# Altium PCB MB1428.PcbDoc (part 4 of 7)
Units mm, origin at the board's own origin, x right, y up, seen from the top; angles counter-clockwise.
Board outline 55.88 x 152.4 mm, 4 copper layers (Top Layer, Signal Layer 1, Signal Layer 2, Bottom Layer), stack 1.614 mm thick; 396 components, 227 nets, 1346 pads, 1469 vias.
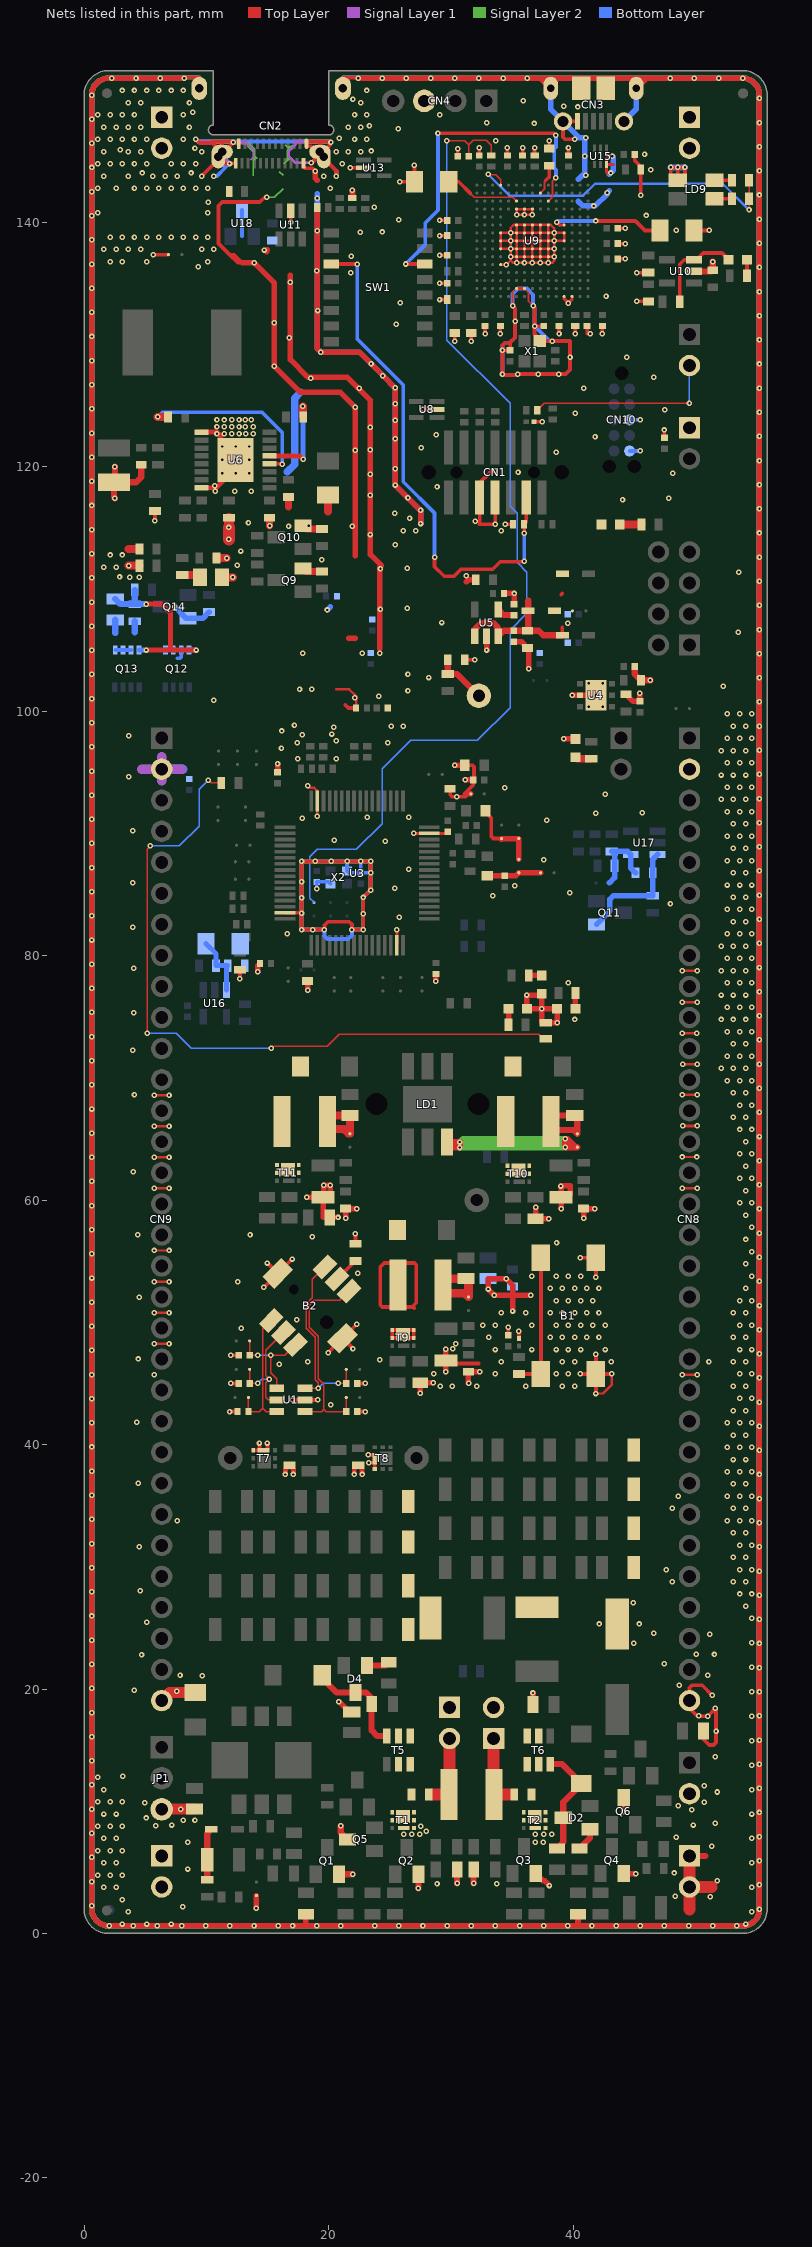
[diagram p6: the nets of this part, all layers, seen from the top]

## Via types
v1: diameter 0.45, hole 0.2, Top Layer to Bottom Layer, tented both sides, 1460 vias
v2: diameter 0.6, hole 0.2, Top Layer to Bottom Layer, tented both sides, 9 vias

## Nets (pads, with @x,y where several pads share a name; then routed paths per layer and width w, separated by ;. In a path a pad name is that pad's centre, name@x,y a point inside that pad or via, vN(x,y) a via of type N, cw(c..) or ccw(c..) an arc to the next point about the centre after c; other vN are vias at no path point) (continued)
GND: B1.3 B1.4 B2.7 B2.8 C4.1 C5.1 C6.1 C7.2 C8.1 C9.1 C10.1 C11.1 C12.1 C13.1 C14.1 C15.1 C16.1 C18.1 C19.1 C23.1 C24.1 C25.1 C30.1 C32.1 C33.1 C34.1 C35.1 C36.1 C37.1 C38.1 C39.1 C40.1 C41.1 C42.1 C43.1 C44.1 C45.1 C46.1 C47.1 C48.1 C49.1 C51.2 C52.1 C53.1 C54.1 C55.1 C56.1 C59.1 C60.1 C61.1 C62.1 C63.1 C64.1 C65.1 C66.1 C67.1 C68.1 C69.1 C70.1 C71.1 C72.1 C73.1 C74.1 C75.1 C76.1 C77.1 C78.1 C79.1 C80.1 C81.1 C82.1 C83.1 C84.1 C85.1 C86.1 C87.1 C89.1 C92.1 C93.1 C97.1 C98.1 C99.1 C100.1 C101.1 C103.1 C104.1 C105.1 CN1.5 CN1.7 CN2.1 CN2.2 CN2.3 CN2.4 CN2.5 CN2.6 CN2.A1 CN2.A12 CN2.B1 CN2.B12 CN3.5 CN3.6 CN3.7 CN3.8 CN3.9 CN3.10 CN3.11 CN4.3 CN5.1 CN5.2 CN6.1 CN6.2 CN7.2 CN8.2 CN8.32 CN9.2 CN9.32 CN10.3 CN10.5 CN11.1 CN11.2 CN12.1 CN12.2 JP1.3 JP6.1 L7.1 LD2.2 LD3.2 LD4.2 LD5.2 LD6.2 LD7.2 LD9.1 Q1.2 Q2.2 Q3.2 Q4.2 Q5.3 Q6.3 Q9.2 Q10.2 Q14.2 R1.1 R7.1 R12.1 R13.1 R59.1 R60.1 R66.1 R68.1 R70.1 R71.1 R73.1 R76.1 R77.1 R83.1 R98.1 R101.1 R103.1 R106.1 R108.1 R109.1 R118.1 R120.1 R122.2 R124.1 R126.2 R131.1 R135.1 R141.1 SB1.2 SB25.1 SB32.1 T1.4 T1.7 T2.4 T2.7 T7.4 T7.7 T8.4 T8.7 U1.2 U2.2 U3.15 U3.31 U3.47 U3.63 U4.2 U4.EP U5.2 U6.1 U6.8 U6.17 U7.2 U8.2 U9.D5 U9.D7 U9.D8 U9.D9 U9.F2 U9.F6 U9.F7 U9.F8 U9.F9 U9.F10 U9.F12 U9.G2 U9.G6 U9.G7 U9.G8 U9.G9 U9.G10 U9.G12 U9.H6 U9.H7 U9.H8 U9.H9 U9.H10 U9.H12 U9.J6 U9.J7 U9.J8 U9.J9 U9.J10 U9.K6 U9.K7 U9.K8 U9.K9 U9.K10 U9.M1 U9.M8 U9.M9 U9.N1 U10.2 U11.2 U12.2 U13.2 U14.2 U15.3 U18.3 X1.2 X2.2 X2.4 | length 1905
  Top Layer w0.15: v1(35.055,133.15) 35.055,134.25 U9.F2@35.38,134.575 ; U9.G2@36.03,134.575 36.36,134.245 36.36,133.52 v1(36.73,133.15)
  Top Layer w0.2: v1(5.75,48.25) v1(6.95,48.25) ; v1(5.75,50.8) v1(6.95,50.8) ; v1(5.75,53.325) v1(6.95,53.325) ; v1(5.75,55.875) v1(6.95,55.875) ; v1(5.75,60.95) v1(6.95,60.95) ; v1(5.75,63.5) v1(6.95,63.5) ; v1(5.75,66.025) v1(6.95,66.025) ; v1(5.75,68.575) v1(6.95,68.575) ; CN2.A1@17.945,144.53 17.945,144.555 CN2.A1@17.945,144.82 ; v1(18.289,93.879) 18.444,93.724 18.83,93.724 19.089,93.465 U3.47@19.089,92.654 v1(19.089,91.404) ; 20.645,101.78 21.695,101.78 22.25,101.225 C37.1@22.25,100.25 ; v1(29.595,47.8) v1@29.689,47.8 ; U9.D5@34.08,136.525 v1(34.555,136.525) 34.905,136.875 ; v1(41.875,44.175) 42.449,44.175 43.175,44.901 v1(43.175,45.775) ; v1(48.925,63.525) v1(50.125,63.525) ; v1(48.925,73.65) v1(50.125,73.65) ; v1(48.95,45.7) v1(50.15,45.7) ; v1(48.95,60.95) v1(50.15,60.95) ; v1(48.95,68.6) v1(50.15,68.6) ; v1(48.95,76.2) v1(50.15,76.2) ; v1(48.95,78.75) v1(50.15,78.75) ; v1(48.975,71.125) v1(50.175,71.125) ; U9.D8@34.08,138.475 v1(34.905,138.475) ; U9.D8@34.08,138.475 U9.D7@34.08,137.825 v1(34.905,137.825) ; U9.D8@34.08,138.475 U9.D9@34.08,139.125 v1(34.905,139.125) ; 34.905,136.875 v1(34.905,137.175) ; 34.905,136.875 35.08,136.7 v1(35.38,136.7) ; v1(34.905,137.175) U9.F6@35.38,137.175 ; v1(34.905,137.175) v1(34.905,137.825) ; v1(34.905,137.825) U9.F7@35.38,137.825 ; v1(34.905,137.825) v1(34.905,138.475) ; v1(34.905,138.475) U9.F8@35.38,138.475 ; v1(34.905,138.475) v1(34.905,139.125) ; v1(34.905,139.125) U9.F9@35.38,139.125 ; v1(34.905,139.125) 34.905,139.55 35.13,139.775 U9.F10@35.38,139.775 ; v1(35.38,136.7) U9.F6@35.38,137.175 ; v1(35.38,136.7) v1(36.03,136.7) ; U9.F6@35.38,137.175 U9.G6@36.03,137.175 ; U9.F6@35.38,137.175 U9.F7@35.38,137.825 ; U9.F7@35.38,137.825 U9.F8@35.38,138.475 ; U9.F7@35.38,137.825 U9.G7@36.03,137.825 ; U9.F8@35.38,138.475 U9.F9@35.38,139.125 ; U9.F8@35.38,138.475 U9.G8@36.03,138.475 ; U9.F9@35.38,139.125 U9.F10@35.38,139.775 ; U9.F9@35.38,139.125 U9.G9@36.03,139.125 ; U9.F10@35.38,139.775 U9.G10@36.03,139.775 ; v1(36.03,136.7) U9.G6@36.03,137.175 ; v1(36.03,136.7) v1(36.68,136.7) ; U9.G6@36.03,137.175 U9.H6@36.68,137.175 ; U9.G6@36.03,137.175 U9.G7@36.03,137.825 ; U9.G7@36.03,137.825 U9.G8@36.03,138.475 ; U9.G7@36.03,137.825 U9.H7@36.68,137.825 ; U9.G8@36.03,138.475 U9.G9@36.03,139.125 ; U9.G8@36.03,138.475 U9.H8@36.68,138.475 ; U9.G9@36.03,139.125 U9.G10@36.03,139.775 ; U9.G9@36.03,139.125 U9.H9@36.68,139.125 ; U9.G10@36.03,139.775 U9.H10@36.68,139.775 ; v1(36.03,140.6) U9.G12@36.03,141.075 ; v1(36.03,140.6) v1(36.68,140.6) U9.H12@36.68,141.075 U9.G12@36.03,141.075 ; v1(36.03,140.6) v1(35.38,140.6) U9.F12@35.38,141.075 U9.G12@36.03,141.075 ; v1(36.68,136.7) U9.H6@36.68,137.175 ; v1(36.68,136.7) v1(37.33,136.7) ; U9.H6@36.68,137.175 U9.J6@37.33,137.175 ; U9.H6@36.68,137.175 U9.H7@36.68,137.825 ; U9.H7@36.68,137.825 U9.H8@36.68,138.475 ; U9.H7@36.68,137.825 U9.J7@37.33,137.825 ; U9.H8@36.68,138.475 U9.H9@36.68,139.125 ; U9.H8@36.68,138.475 U9.J8@37.33,138.475 ; U9.H9@36.68,139.125 U9.H10@36.68,139.775 ; U9.H9@36.68,139.125 U9.J9@37.33,139.125 ; U9.H10@36.68,139.775 U9.J10@37.33,139.775 ; v1(37.33,136.7) U9.J6@37.33,137.175 ; v1(37.33,136.7) v1(37.98,136.7) ; U9.J6@37.33,137.175 U9.J7@37.33,137.825 ; U9.J6@37.33,137.175 U9.K6@37.98,137.175 ; U9.J7@37.33,137.825 U9.J8@37.33,138.475 ; U9.J7@37.33,137.825 U9.K7@37.98,137.825 ; U9.J8@37.33,138.475 U9.J9@37.33,139.125 ; U9.J8@37.33,138.475 U9.K8@37.98,138.475 ; U9.J9@37.33,139.125 U9.J10@37.33,139.775 ; U9.J9@37.33,139.125 U9.K9@37.98,139.125 ; U9.J10@37.33,139.775 U9.K10@37.98,139.775 ; v1(37.98,136.7) U9.K6@37.98,137.175 ; v1(37.98,136.7) 38.33,136.7 38.455,136.825 v1(38.455,137.175) ; U9.K6@37.98,137.175 v1(38.455,137.175) ; U9.K6@37.98,137.175 U9.K7@37.98,137.825 ; U9.K7@37.98,137.825 v1(38.455,137.825) ; U9.K7@37.98,137.825 U9.K8@37.98,138.475 ; U9.K8@37.98,138.475 U9.K9@37.98,139.125 ; U9.K8@37.98,138.475 v1(38.455,138.475) ; U9.K9@37.98,139.125 U9.K10@37.98,139.775 ; U9.K9@37.98,139.125 v1(38.455,139.125) ; U9.K10@37.98,139.775 38.18,139.775 38.455,139.5 v1(38.455,139.125) ; v1(38.455,137.175) v1(38.455,137.825) ; v1(38.455,137.825) v1(38.455,138.475) ; v1(38.455,138.475) U9.M8@39.28,138.475 U9.M9@39.28,139.125 v1(38.455,139.125) ; v1(38.455,138.475) v1(38.455,139.125)
  Top Layer w0.25: U3.63@16.439,83.504 17.739,83.504 v1(17.789,83.454) ; U3.15@25.589,80.854 v1(25.589,82.104) ; v1(26.989,90.004) U3.31@28.239,90.004 29.629,90.004 C30.1@29.75,90.125 ; U9.F2@35.38,134.575 U9.G2@36.03,134.575 ; U9.M1@39.28,133.925 39.28,133.725 39.605,133.4 v1(39.605,133.375) 39.93,133.7 U9.N1@39.93,133.925 ; v1(43.075,144.025) 42.8,144.025 42.75,144.075 U15.3@42.75,144.75 ; v1(43.225,145.4) 42.925,145.4 42.75,145.225 U15.3@42.75,144.75 ; 43.3,144.725 42.775,144.725 U15.3@42.75,144.75 ; v1(48.975,66.075) 49.002,66.048 50.148,66.048 v1(50.175,66.075)
  Top Layer w0.3: v1(5.675,137.35) SB32.1@6.9,137.35 ; v1(5.8,115.575) R109.1@5.8,116.375 ; 7.9,151.85 9.425,151.85 CN2.6@9.425,150.95 ; v1@9.145,146.781 9.451,146.475 10.513,146.475 10.98,146.008 CN2.4@10.98,145.35 ; v1@9.645,143.78 9.645,143.795 10.525,144.675 10.65,144.675 10.98,145.005 CN2.4@10.98,145.35 ; 10.535,146.6 11.3,146.6 ; v1(11.9,42.7) C10.1@12.55,42.7 ; v1(12,45) C12.1@12.65,45 ; v1(12,47.3) C15.1@12.65,47.3 ; CN2.A12@12.405,144.82 11.92,144.82 v1(11.9,144.8) 11.53,144.8 CN2.4@10.98,145.35 ; CN2.B1@12.655,146.205 CN2.B1@12.655,146.42 12.55,146.525 v1(12.2,146.525) ; v1(12.75,78.1) R83.1@12.75,78.85 ; T7.4@13.85,39.525 T7.7@14.5,39.525 ; v1(14.35,40.125) 14.35,39.675 T7.7@14.5,39.525 ; v1(14.7,52.853) B2.7@15.848,54.002 ; v1@14.975,142.025 v1(14.95,142.05) 14.775,142.05 14.375,141.65 11.3,141.65 10.995,141.345 10.995,138.255 11.9,137.35 ; v1(15,40.125) 15,39.7 14.825,39.525 T7.7@14.675,39.525 T7.7@14.5,39.525 ; v1(15,54.85) B2.7@15.848,54.002 ; v1(16.9,140) U11.2@16.9,140.925 ; v1(17.025,43.65) U1.2@18.075,43.65 v1(19.125,43.65) ; v1(17.025,55.178) B2.7@15.848,54.002 ; CN2.A1@17.945,144.555 18.075,144.425 18.675,144.425 v1(18.925,144.175) ; CN2.A1@17.945,144.82 CN2.A1@17.945,144.97 ; v1(18.6,144.85) CN2.2@19.295,145.545 ; v1(19.975,47.522) B2.8@21.152,48.698 ; v1(20.2,146.525) v1@20.125,146.6 ; v1@20.645,143.78 20.645,144.183 19.295,145.533 CN2.2@19.295,145.545 ; CN2.3@21.175,150.95 21.175,151.825 22.375,151.825 v1(22.425,151.775) ; 21.375,100.5 21.625,100.25 C37.1@22.25,100.25 ; v1(21.78,144.45) U13.2@22.855,144.45 ; v1(22,47.85) B2.8@21.152,48.698 ; R70.1@22.2,56.425 v1(22.2,57.25) ; v1(22.3,49.847) B2.8@21.152,48.698 ; C11.1@22.35,42.7 v1(23,42.7) ; C13.1@22.35,45 v1(23,45) ; v1(23.25,39.15) 23.6,39.15 23.775,38.975 T8.7@23.775,38.825 T8.7@23.775,38.65 ; v1(23.275,38.5) 23.625,38.5 T8.7@23.775,38.65 ; T8.4@23.775,38 T8.7@23.775,38.65 ; v1(25.83,143.3) C78.1@27.03,143.3 v1(27.03,144.65) ; v1(27.698,124.682) U8.2@28.875,124.682 ; v1(29.08,133.675) R120.1@29.705,133.675 ; v1(29.08,135) C70.1@29.705,135 ; v1(29.08,137.3) C72.1@29.705,137.3 ; v1(29.08,138.9) C75.1@29.705,138.9 ; v1(29.08,140.15) C77.1@29.705,140.15 ; R68.1@29.6,46.875 29.85,46.625 32.3,46.625 ; C32.1@29.95,93.65 29.95,93.15 30.1,93 v1(30.5,93) 31.2,93 31.429,93.229 ; v1(30.33,130.275) C60.1@30.33,130.925 ; C84.1@30.58,145.4 v1(30.58,146.025) ; 31.107,93.229 31.839,93.961 C34.1@31.839,94.379 31.9,94.44 31.9,95.45 31.771,95.579 L7.1@31.139,95.579 ; C41.1@31.15,104.2 v1(31.95,104.2) ; v1(31.68,130.275) C61.1@31.68,130.925 ; C79.1@32.33,145.45 v1(32.33,146.075) ; v1(32.805,130.875) C62.1@32.805,131.5 ; v1(33.6,119.65) 33.3,119.65 33.195,119.545 33.195,119.495 32.78,119.08 32.73,119.08 32.365,118.715 CN1.5@32.365,117.493 32.365,115.292 32.355,115.282 v1(33.625,115.282) 33.635,115.292 CN1.7@33.635,117.493 ; v1(34.055,130.875) C63.1@34.055,131.5 ; v1(34.444,115.282) 34.447,115.285 R106.1@35.1,115.285 ; C80.1@34.63,145.45 v1(34.63,146.075) ; C16.1@34.7,48.95 v1(34.7,49.6) ; v1(35.055,133.15) 35.26,132.945 v1(35.26,131.905) 35.26,130.555 34.855,130.15 ; U2.2@35.575,48.687 v1(35.575,49.275) ; C81.1@35.88,145.45 v1(35.88,146.075) ; v1(36.73,133.15) 36.855,133.025 v1(36.855,131.5) ; U7.2@36.797,123.675 37.493,123.675 v1(37.486,123.682) ; R131.1@36.855,145.45 v1(36.855,146.075) ; C64.1@37.53,131.425 C64.1@37.605,131.5 v1(36.855,131.5) ; C82.1@38.055,146.025 v1(38.055,146.65) ; v1(38.855,130.875) C65.1@38.855,131.5 ; C83.1@39.63,145.45 v1(39.63,146.075) ; v1(39.755,128.95) v1@39.75,128.955 ; v1@40.145,146.781 39.344,146.781 39.175,146.95 CN3.7@39.175,148.25 CN3.5@40.375,148.25 ; v1(40.18,130.875) R118.1@40.18,131.5 ; v1(40.575,45.775) B1.3@41.875,45.775 ; v1(40.575,55.275) B1.4@41.875,55.275 v1(41.875,53.675) ; 41.155,130.875 C66.1@41.155,131.5 ; v1(41.875,44.175) B1.3@41.875,45.775 ; v1(41.875,47.375) B1.3@41.875,45.775 ; v1(42.405,130.875) C67.1@42.405,131.5 ; v1(43.175,45.775) B1.3@41.875,45.775 ; C71.1@43.655,137 v1(44.28,137) ; C73.1@43.655,138.25 v1(44.28,138.25) ; C76.1@43.655,139.5 v1(44.28,139.5) ; v1(44.15,9.975) Q6.3@44.15,11.1 ; C85.1@45.05,145.55 45.05,145.05 45.55,144.55 U14.2@45.55,144.3 v1(45.55,142.2) ; v1(45.205,135.875) R122.2@46.155,135.875 ; v1(45.23,133.525) C68.1@46.18,133.525 ; C56.1@47.475,122.375 v1(47.475,123) ; LD9.1@47.985,143.42 v1(47.985,144.48) v1@48.575,144.48 ; LD9.1@48.575,143.425 v1@48.575,144.48 ; v1(48.575,144.485) v1@48.575,144.48 ; LD9.1@49.16,143.42 v1(49.16,144.48) v1@48.575,144.48 ; C74.1@49.905,139.325 v1(51.13,139.325) ; C5.1@50.675,16.55 50.675,15.9 51.15,15.425 51.5,15.425 51.7,15.625 v1(51.7,16.55) 51.7,18.375 v1(51.65,18.425) 51.65,18.4 v1(51.025,17.775) 50.175,17.775 49.53,18.42 49.53,20.108 49.725,20.303 50.572,20.303 v1(51.4,19.475) ; 11.3,146.6 11.305,146.595 CN2.5@11.305,145.75 11.425,145.75 v1(12.2,146.525) ; 11.3,146.6 12.125,146.6 v1(12.2,146.525) ; 11.9,137.35 12.575,136.675 12.925,136.675 12.25,137.35 11.9,137.35 ; CN2.2@19.295,145.545 CN2.2@19.295,145.75 ; CN2.2@19.295,145.75 19.295,146.595 19.3,146.6 ; CN2.2@19.295,145.75 19.545,145.5 19.545,145.707 20.125,146.287 v1@20.125,146.6 ; CN2.2@19.295,145.75 19.025,145.75 18.575,146.2 18.2,146.2 18.195,146.205 CN2.B12@18.195,146.42 18.195,146.595 18.2,146.6 19.3,146.6 ; 19.3,146.6 v1@20.125,146.6 ; v1(34.23,129.525) 34.23,127.579 v1(34.231,127.578) 34.304,127.505 35.385,127.505 35.455,127.575 v1(35.48,127.575) v1(37.155,127.575) v1(38.83,127.575) 39.405,127.575 39.75,127.92 v1@39.75,128.955 ; v1(34.23,129.525) 34.23,129.925 34.455,130.15 34.855,130.15 ; v1(34.23,129.525) C59.1@34.855,129.525 34.855,130.15 ; v1(36.855,131.5) 36.855,130.85 37.28,130.425 X1.2@37.28,130.275 v1(38.305,130.275) 39.73,130.275 39.75,130.255 v1@39.75,128.955 ; v1(17.789,82.129) v1(18.726,82.129) v1(19.664,82.129) 19.664,82.479 19.964,82.779 21.689,82.779 21.914,82.554 v1(21.914,82.129) v1(22.839,82.129) v1(22.839,83.441) v1(22.839,84.754) v1(23.439,85.354) v1(23.439,86.779) v1(23.439,87.704) v1(22.639,87.704) v1(21.514,87.704) v1(20.214,87.704) v1(18.914,87.704) v1(17.789,87.704) v1(17.789,86.029) v1(17.789,84.729) v1(17.789,83.454) v1(17.789,82.129)
  Top Layer w0.4: U6.8@9.625,118.275 10.825,118.275 11.138,118.588 ; U6.1@9.625,122.825 10.875,122.825 11.15,122.55 11.15,121.8 v2(11.3,121.65) v2(12.4,120.55) ; v1(16.475,37.55) 16.475,37.975 R59.1@16.8,38.3 17.125,37.975 v1(17.125,37.55) ; v1(22.1,37.55) 22.1,37.975 R60.1@22.425,38.3 22.75,37.975 v1(22.75,37.55) ; 11.138,118.588 11.138,119.288 v2(11.3,119.45) v2(12.4,120.55) ; 11.138,118.588 12.4,119.85 v2(12.4,120.55)
  Top Layer w0.45: v1(2.053,0.625) cw(c2.053,2.053) 1.787,0.65 ; v1(8.2,151.775) 2,151.775 ccw(c2,150.4) v1(0.625,150.4) 0.625,4.325 0.625,2.053 ccw(c2.053,2.053) 1.787,0.65 ; 12.925,136.675 v1(13.925,136.675) 15.575,135.025 v1(15.575,131.775) v1(15.575,128.2) 17.7,126.075 20.975,126.075 v1(22.175,124.875) v1(22.175,121.35) 22.175,112.692 ; v1(14.1,2.05) SB1.2@14.1,3.1 ; v1(14.2,78.675) 14.2,79.15 C25.1@14.4,79.35 ; 14.95,137.575 14.95,137.725 14.975,137.75 ; C33.1@15.825,95 v1(15.825,95.7) ; 16.875,135.65 v1(16.875,135.075) 16.875,128.75 18.325,127.3 21.55,127.3 23.425,125.425 v1(23.425,123.225) v1(23.425,121.4) v1(23.425,119.375) v1(23.425,117.675) v1(23.425,114.45) 23.425,112.812 24.175,112.062 24.175,112.05 24.325,111.9 24.175,111.75 24.175,105.1 ; R1.1@18.15,1.575 18.15,0.675 18.175,0.65 ; v1(18.225,60.225) R77.1@19.55,60.225 ; v1(18.289,77.161) C23.1@18.289,77.929 ; v1(18.925,144.175) 18.925,143.575 19.075,143.425 ; R124.1@19.075,141.2 v1(19.075,139.3) 19.075,129.675 v1(19.375,129.375) 22.525,129.375 v1(24.45,127.45) v1(25.45,126.45) 25.425,126.425 25.45,126.4 v1(25.45,125.15) 25.45,123.85 25.425,123.825 v1(25.45,123.8) v1(25.45,122.3) v1(25.45,119.825) v1(25.45,118.5) v1(27.525,116.425) v1(27.525,115.35) ; v1(20.775,58.575) R71.1@20.1,58.575 19.55,58.575 R77.1@19.55,60.225 ; v1(20.85,18.975) 21.7,18.125 C6.1@21.9,18.125 ; v1(21.405,58.525) 21.4,58.53 C19.1@21.4,59.3 22.32,59.3 v1(22.325,59.305) ; 21.65,105.95 22.175,105.95 ; v1(22.425,151.775) 37.675,151.775 ; v1(27.5,44.2) R66.1@27.5,45.05 v1(28.55,45.05) ; v1(28.789,77.904) C24.1@28.789,78.504 ; v1(29.595,47.8) 29.6,47.795 R68.1@29.6,46.875 v1(29.6,45.95) ; v1(29.703,0.625) 49.3,0.625 53.88,0.625 ccw(c53.88,2) v1(55.255,2) 55.255,2.428 55.25,2.428 55.25,150.405 ccw(c53.88,150.405) v1(53.88,151.775) 46,151.775 ; v1@29.703,0.65 18.175,0.65 ; v1(30.314,95.579) L7.1@31.139,95.579 ; v1(31.189,94.379) C34.1@31.839,94.379 ; 31.275,110.575 31.45,110.75 C47.1@32.05,110.75 ; 31.429,93.229 SB25.1@31.639,93.229 ; v1(31.455,45.025) 31.45,45.03 C14.1@31.45,45.95 32.37,45.95 v1(32.375,45.955) ; v1(32.925,105) U5.2@32.925,106.125 ; C45.1@34.35,109.625 v1(35.175,109.625) C44.1@35.175,108.75 ; v1(35.05,50.925) 35.05,52.225 ; C43.1@35.15,105.675 35.775,105.675 C42.1@36.275,105.175 36.385,105.065 v1(36.385,103.455) ; v1(36.525,52.225) 35.05,52.225 ; v1(36.94,59.4) 36.945,59.395 R73.1@36.945,58.475 v1(38,58.475) ; Q3.2@36.95,4.9 37.525,4.325 37.675,4.325 v1(38.075,3.925) ; 37.15,151.775 37.35,151.775 ; v1(39.025,59.3) 39.02,59.305 R76.1@39.02,60.225 ; v1(39.25,97.725) LD6.2@40.2,97.725 ; v1(39.95,101.3) U4.2@40.575,101.3 v1(41.875,101.3) ; v1(40.875,58.525) 40.87,58.53 C18.1@40.87,59.3 41.79,59.3 v1(41.795,59.305) ; Q4.2@44.15,4.9 v1(45.125,4.9) ; C36.1@44.35,101.375 44.925,100.8 C35.1@45.475,100.8 v1(45.475,101.475) ; CN3.9@45.175,150.95 46,151.775 ; 1.787,0.65 18.175,0.65 ; R77.1@19.55,60.225 R77.1@19.6,60.275 ; R77.1@19.6,60.275 v1(19.6,61.225) v1(20.15,61.225) 20.15,60.45 19.6,59.9 R77.1@19.6,60.275 ; 35.05,52.225 35.05,53.05 v1(34.525,53.575) 33.05,53.575 v1(33.05,52.725) 33.55,52.225 v1(33.575,52.225) 35.05,52.225 ; 37.35,151.775 CN3.8@38.175,150.95 cw(c39,150.95) 39,151.775 ; 37.35,151.775 39,151.775 ; v1(37.45,75.65) 37.45,74.55 37.475,74.525 v1(38.7,74.525) LD4.2@38.7,75.65 v1(37.45,75.65) ; v1(37.45,75.65) LD5.2@37.45,76.875 37.35,76.775 v1(36.225,76.775) LD3.2@36.225,75.65 v1(37.45,75.65) ; 39,151.775 46,151.775 ; R76.1@39.02,60.225 39.55,60.225 39.775,60.45 39.775,61.175 39.04,61.175 v1(39.015,61.15) 39.02,61.145 R76.1@39.02,60.225
  Top Layer w0.5: v1(2.525,117.4) 2.45,117.475 C54.1@2.45,118.725 ; v1(2.525,120) 2.525,118.8 C54.1@2.45,118.725 ; C55.1@4.675,120.15 4.675,119.15 4.25,118.725 C54.1@2.45,118.725 ; Q1.2@20.85,4.85 v1(21.975,4.85) ; v1(21,8.8) 21,8.25 Q5.3@21.55,7.7 ; R126.2@21.955,141.975 v1(21.955,142.6) ; v1(27.35,3.7) Q2.2@27.35,4.85 ; v1(30.525,4.1) R12.1@30.525,5.25 ; v1(31.875,4.1) R13.1@31.875,5.25 ; C9.1@36.725,18.725 v1(36.725,19.675) ; 40.375,0.65 40.4,0.675 R7.1@40.4,1.575 ; C40.1@45.05,103.65 45.05,103.025 C39.1@45.55,102.525 v1(46.325,102.525) ; CN5.1@49.53,6.35 50.828,6.35 ; U10.2@49.905,135.975 51.33,135.975 C69.1@51.43,136.075 v1(51.43,136.775)
  Top Layer w0.6: v1(15.175,115.15) C51.2@15.175,115.825 ; 16.725,116.7 C53.1@16.725,117.525 ; Q9.2@17.925,111.675 18.175,111.425 R98.1@19.475,111.425 ; Q10.2@17.925,115.175 18.2,114.9 R103.1@19.475,114.9
  Top Layer w0.65: v1(3.65,111.9) R101.1@4.525,111.9 ; 3.65,113.275 C49.1@4.525,113.275 ; C48.1@10.825,112.525 v1(11.675,112.525) ; C46.1@11.25,110.95 v1(12.175,110.95) ; 19.95,116.325 C52.1@19.95,117.675
  Top Layer w0.8: v1(11.85,115.025) R108.1@11.85,115.825
  Top Layer w0.9: JP1.3@6.35,10.16 6.365,10.175 C4.1@9.025,10.175 ; CN9.32@6.35,19.05 7,19.7 C8.1@9.1,19.7
  Top Layer w1: v1(11.85,114.05) v1(11.85,115.025) ; 49.53,1.98 CN5.2@49.53,3.81 ; CN5.1@49.53,6.35 CN5.2@49.53,3.81 ; 51.34,3.81 CN5.2@49.53,3.81
  Signal Layer 1 w0.15: 13.225,146.525 13.87,145.88 13.87,145.345 13.65,145.125
  Signal Layer 1 w0.2: 17.325,146.6 17.325,146.379 16.73,145.784 16.73,145.416 17.296,144.85 v1(18.6,144.85)
  Signal Layer 1 w0.3: v1(8.2,151.775) 8.275,151.85 9.325,151.85 9.425,151.75 CN2.6@9.425,150.95 ; v1@9.145,146.781 9.326,146.6 11.225,146.6 ; v1(11.9,144.8) 11.35,145.35 CN2.4@10.98,145.35 10.98,145.575 11.225,145.82 11.225,146.6 ; 13.225,146.525 v1(12.2,146.525) 12.225,146.55 12.175,146.6 11.225,146.6 ; 17.325,146.6 19.475,146.6 ; v1(18.6,144.85) 19.295,145.545 CN2.2@19.295,145.75 19.295,146.42 19.475,146.6 ; v1(20.2,146.525) 20.125,146.6 19.475,146.6 ; CN2.3@21.175,150.95 21.175,151.825 21.2,151.85 22.35,151.85 v1(22.425,151.775)
  Signal Layer 1 w0.8: 4.75,95.25 CN9.2@6.35,95.25 ; 6.35,94.3 CN9.2@6.35,95.25 ; 6.35,96.265 CN9.2@6.35,95.25 ; 8,95.25 CN9.2@6.35,95.25
  Signal Layer 2 w0.12: v1(12.2,146.525) 13.4,146.525 ; 13.855,143.8 13.855,145.009 ; 14.159,145.218 14.137,145.218 13.945,145.41 ; v1(14.95,142.05) 15.575,142.05 16.275,142.75 ; 15.975,144.125 16.275,143.825 ; 16.35,144.8 16.65,145.1 ; 16.45,146.325 16.65,146.125 ; 13.4,146.525 13.4,146.223 13.855,145.768 13.855,145.5 ; 13.4,146.525 13.95,145.975 13.95,145.773 13.945,145.768 13.945,145.41 ; 13.855,145.009 13.945,145.099 13.945,145.41 ; 13.855,145.009 13.855,145.5 ; 13.855,145.5 13.945,145.41
  Signal Layer 2 w0.2: 16.73,146.13 16.775,146.175 ; 17,146.054 17,146.175
  Signal Layer 2 w0.25: 16.65,145.1 16.705,145.155 16.705,145.88 17,146.175
  Signal Layer 2 w0.3: v1(8.2,151.775) 8.25,151.825 9.425,151.825 CN2.6@9.425,150.95 ; v1@9.145,146.781 9.326,146.6 11.225,146.6 ; v1(11.9,144.8) 11.35,145.35 CN2.4@10.98,145.35 10.98,145.78 11.225,146.025 11.225,146.6 ; v1(12.2,146.525) 12.125,146.6 11.225,146.6 ; 17.9,146.6 19.325,146.6 ; v1(18.6,144.85) 19.295,145.545 CN2.2@19.295,145.75 ; CN2.2@19.62,145.208 CN2.1@19.62,145.35 19.62,145.425 CN2.2@19.295,145.75 ; v1(19.664,82.129) v1(18.726,82.129) v1(17.789,82.129) v1(17.789,83.454) v1(17.789,84.729) v1(17.789,86.029) v1(17.789,87.704) v1(18.914,87.704) v1(20.214,87.704) v1(21.514,87.704) v1(22.639,87.704) v1(23.439,87.704) v1(23.439,86.779) v1(23.439,85.354) v1(22.839,84.754) v1(22.839,83.441) v1(22.839,82.129) v1(21.914,82.129) ; v1(20.2,146.525) 20,146.525 19.925,146.6 19.325,146.6 ; v1@20.645,143.78 20.645,144.183 ; CN2.3@21.175,150.95 21.175,151.85 v1@22.525,151.85 ; CN2.2@19.295,145.75 19.295,146.37 19.325,146.4 19.325,146.6
  Signal Layer 2 w0.45: v1@5.203,0.65 31.653,0.65 v1(31.678,0.625) 49.3,0.625 53.88,0.625 ccw(c53.88,2) v1(55.255,2) 55.255,2.428 55.25,2.428 55.25,150.405 ccw(c53.88,150.405) v1(53.88,151.775) v1(22.425,151.775) ; v1(6.003,0.625) v1(2.053,0.625) cw(c2.053,2.053) 0.625,2.053 0.625,4.325 v1(0.625,150.4) cw(c2,150.4) 2,151.775 v1(8.2,151.775)
  Bottom Layer w0.3: v1@8.375,151.85 9.45,151.85 9.425,151.825 CN2.6@9.425,150.95 ; v1@9.145,146.781 9.326,146.6 11.275,146.6 ; v1@10.645,143.78 10.88,143.78 11.55,144.45 ; v1(12.2,146.525) v1@12.125,146.6 ; 12.925,138.875 U18.3@12.925,141.025 ; v1(17.789,87.704) v1(17.789,86.029) v1(17.789,84.729) v1(17.789,83.454) v1(17.789,82.129) v1(18.726,82.129) v1(19.664,82.129) 19.664,81.604 19.914,81.354 21.614,81.354 21.914,81.654 v1(21.914,82.129) v1(22.839,82.129) v1(22.839,83.441) v1(22.839,84.754) v1(23.439,85.354) v1(23.439,86.779) ; v1(18.6,144.85) 19.295,145.545 CN2.2@19.295,145.75 19.295,146.22 19.338,146.262 19.338,146.6 ; v1(18.914,87.704) v1(20.214,87.704) v1(21.514,87.704) ; v1(19.039,85.454) C93.1@19.039,86.029 20.014,86.029 X2.4@20.164,85.879 ; v1(20.2,146.525) 20.075,146.525 20,146.6 19.338,146.6 ; CN2.3@21.175,150.95 21.175,151.825 21.2,151.85 22.35,151.85 v1(22.425,151.775) ; v1@35.03,133.15 35.26,132.92 v1(35.26,131.905) 35.26,130.555 34.855,130.15 34.455,130.15 34.23,129.925 v1(34.23,129.525) 34.231,129.524 v1(34.231,127.578) 34.304,127.505 35.41,127.505 v1(35.48,127.575) v1(37.155,127.575) v1(38.83,127.575) 39.405,127.575 39.755,127.925 v1(39.755,128.95) 39.755,130.25 39.73,130.275 v1(38.305,130.275) 38.08,130.275 v1(36.855,131.5) 36.855,133.025 v1(36.73,133.15) 36.73,134.075 36.23,134.575 35.505,134.575 35.055,134.125 v1(35.055,133.15) ; CN10.5@44.63,121.285 v1(45.505,121.285) ; CN10.3@44.63,123.825 v1(45.505,123.825) ; CN2.4@10.98,145.35 11.175,145.545 11.9,144.82 v1(11.9,144.8) ; CN2.4@10.98,145.35 10.98,145.02 11.55,144.45 ; CN2.4@10.98,145.35 11.35,145.35 v1(11.9,144.8) ; CN2.4@10.98,145.35 10.98,145.755 11.275,146.05 11.275,146.6 ; 11.275,146.6 v1@12.125,146.6 ; 11.55,144.45 v1(11.9,144.8) ; v1@12.125,146.6 19.338,146.6 ; v1(21.514,87.704) X2.2@21.514,86.929 21.664,86.779 C92.1@22.639,86.779 ; v1(21.514,87.704) v1(22.639,87.704) ; C92.1@22.639,86.779 v1(23.439,86.779) ; C92.1@22.639,86.779 v1(22.639,87.704) ; v1(22.639,87.704) v1(23.439,87.704) v1(23.439,86.779)
  Bottom Layer w0.45: v1(7.4,108.55) 8.35,107.6 Q14.2@8.5,107.6 9.725,107.6 R141.1@10.225,108.1 ; v1(8.2,151.775) 2,151.775 ccw(c2,150.4) v1(0.625,150.4) 0.625,4.325 0.625,2.053 ccw(c2.053,2.053) v1(2.053,0.625) v1(15.878,0.625) ; 15.078,0.65 29.678,0.65 v1(29.703,0.625) 49.3,0.625 53.88,0.625 ccw(c53.88,2) v1(55.255,2) 55.255,2.428 55.25,2.428 55.25,150.405 ccw(c53.88,150.405) v1(53.88,151.775) v1(22.425,151.775) ; 19.075,142.312 v1(19.075,141.95) v1(19.075,139.3) 19.075,129.675 v1(19.375,129.375) 22.525,129.375 v1(24.45,127.45) v1(25.45,126.45) 25.425,126.425 25.45,126.4 v1(25.45,125.15) 25.45,123.85 25.425,123.825 v1(25.45,123.8) v1(25.45,122.3) v1(25.45,119.825) v1(25.45,118.5) v1(27.525,116.425) v1(27.525,115.35) ; v1(19.9,108.275) 20.15,108.525 ; CN3.8@38.175,150.95 38.175,149.25 CN3.7@39.175,148.25 40.5,146.925 v1(41.025,146.925) 40.95,146.85 v1(40.95,145.4) 40.95,143.9 v1(41.025,143.825) 40.755,143.825 40.43,143.5 ; 40.43,141.7 40.805,141.325 v1(41.705,141.325) 41.805,141.325 42.805,142.325 v1(42.805,142.4) 42.98,142.575 ; v1@42.98,143.93 v1(43.075,144.025) 43.3,144.25 43.3,145.325 v1(43.225,145.4) ; CN3.6@44.175,148.25 45.175,149.25 CN3.9@45.175,150.95
  Bottom Layer w0.5: v1(47.985,144.48) v1(49.16,144.48)
  Bottom Layer w0.6: 16.625,119.575 17.225,120.175 17.225,125.6 17.7,126.075
  Bottom Layer w0.8: CN9.2@6.35,95.25 8.05,95.25
  other v1: 4.028,0.625 7.978,0.625 9.953,0.625 11.928,0.625 13.903,0.625 23.778,0.625 25.753,0.625 27.728,0.625 33.653,0.625 35.628,0.625 37.603,0.625 39.578,0.625 41.553,0.625 43.528,0.625 45.503,0.625 47.478,0.625 49.453,0.625 51.428,0.625 53.403,0.625 17.053,0.65 19.028,0.65 21.003,0.65 3.125,0.775 5.125,0.775 7.125,0.775 54.125,0.775 3.625,1.775 54.625,1.775 8.075,2.175 0.624,2.275 3.125,2.775 51.225,3 48.375,3.05 1.625,3.775 2.625,3.775 54.625,3.775 55.255,3.975 28.875,4.075 33.75,4.075 0.624,4.25 51.8,4.325 1.125,4.775 2.125,4.775 3.125,4.775 48.275,4.95 8.475,5.275 1.625,5.775 2.625,5.775 54.625,5.775 55.255,5.95 0.624,6.225 1.125,6.775 2.125,6.775 3.125,6.775 51.35,7.15 8.5,7.45 36.925,7.45 37.575,7.45 1.625,7.775 2.625,7.775 54.625,7.775 48.45,7.875 55.255,7.925 26.15,8.125 26.8,8.125 27.45,8.125 36.925,8.125 37.6,8.125 38.25,8.125 0.624,8.2 28,8.375 1.125,8.775 2.125,8.775 3.125,8.775 27.55,8.775 5.875,8.825 7.175,8.875 49.85,8.875 51.65,9.025 8.1,9.275 9.075,9.275 5.1,9.45 1.625,9.775 2.625,9.775 54.625,9.775 55.255,9.9 49.725,10.125 7.925,10.15 0.624,10.175 48.625,10.45 4.975,10.7 50.725,10.75 1.125,10.775 2.125,10.775 3.125,10.775 51.8,11.575 1.625,11.775 54.625,11.775 55.255,11.875 50.75,12.075 0.624,12.15 1.125,12.775 3.175,12.85 54.625,13.775 55.255,13.85 0.624,14.125 51.65,14.475 54.625,15.775 55.255,15.825 0.624,16.1 54.625,17.775 50.3,17.8 55.255,17.8 0.624,18.075 54.625,19.775 55.255,19.775 7.575,19.825 4.1,19.9 0.624,20.05 48.7,20.3 9.675,21.1 7.85,21.125 51.025,21.125 55.255,21.75 54.625,21.775 0.624,22.025 47.45,22.075 4.7,22.8 51.575,22.825 50.075,22.85 55.255,23.725 44.975,23.75 54.625,23.775 0.624,24 51.175,24.475 46.6,24.55 42.13,25.319 45.43,25.319 5.125,25.45 55.255,25.7 54.625,25.775 0.624,25.975 54.125,26.775 44.925,27.075 55.255,27.675 53.625,27.775 54.625,27.775 0.624,27.95 4.6,28.025 48.125,28.775 53.125,28.775 54.125,28.775 55.255,29.65 47.625,29.775 53.625,29.775 54.625,29.775 0.624,29.925 53.125,30.775 54.125,30.775 4.5,31.625 55.255,31.625 53.625,31.775 54.625,31.775 0.624,31.9 53.125,32.775 54.125,32.775 55.255,33.6 7.625,33.775 52.625,33.775 53.625,33.775 54.625,33.775 0.624,33.875 48.125,34.775 53.125,34.775 54.125,34.775 55.255,35.575 48.625,35.775 52.625,35.775 53.625,35.775 54.625,35.775 0.624,35.85 53.125,36.775 54.125,36.775 4.425,36.85 55.255,37.55 52.625,37.775 53.625,37.775 54.625,37.775 0.624,37.825 53.125,38.775 54.125,38.775 55.255,39.525 52.625,39.775 53.625,39.775 54.625,39.775 0.624,39.8 53.125,40.775 54.125,40.775 55.255,41.5 0.624,41.775 52.625,41.775 53.625,41.775 54.625,41.775 4.3,41.825 53.125,42.775 54.125,42.775 20.175,43.25 55.255,43.475 0.624,43.75 53.625,43.775 54.625,43.775 29.125,44.775 30.125,44.775 32.125,44.775 36.125,44.775 39.125,44.775 40.125,44.775 53.125,44.775 54.125,44.775 55.255,45.45 0.624,45.725 5.75,45.725 28.625,45.775 33.625,45.775 38.625,45.775 39.625,45.775 53.625,45.775 54.625,45.775 15.975,46.575 18.3,46.775 34.125,46.775 39.125,46.775 40.125,46.775 43.125,46.775 51.125,46.775 53.125,46.775 54.125,46.775 24.2,46.925 4.45,47 55.255,47.425 0.624,47.7 33.625,47.775 36.625,47.775 38.625,47.775 39.625,47.775 40.625,47.775 42.625,47.775 53.625,47.775 54.625,47.775 30.15,47.825 30.425,48.25 33.125,48.775 38.125,48.775 39.125,48.775 40.125,48.775 41.125,48.775 42.125,48.775 53.125,48.775 54.125,48.775 55.255,49.4 12.85,49.525 0.624,49.675 32.625,49.775 33.625,49.775 36.625,49.775 38.625,49.775 39.625,49.775 40.625,49.775 41.625,49.775 42.625,49.775 53.625,49.775 54.625,49.775 17.4,50.2 34.125,50.775 36.125,50.775 38.125,50.775 39.125,50.775 40.125,50.775 41.125,50.775 42.125,50.775 53.125,50.775 54.125,50.775 55.255,51.375 0.624,51.65 38.625,51.775 39.625,51.775 40.625,51.775 41.625,51.775 53.625,51.775 54.625,51.775 4.5,52.05 38.125,52.775 39.125,52.775 40.125,52.775 41.125,52.775 42.125,52.775 54.125,52.775 12.575,53.325 55.255,53.35 0.624,53.625 36.625,53.775 38.625,53.775 39.625,53.775 40.625,53.775 54.625,53.775 22.375,54 54.125,54.775 55.255,55.325 0.624,55.6 54.625,55.775 38.65,56.525 54.125,56.775 18.675,57 4.4,57.15 13.575,57.15 55.255,57.3 0.624,57.575 54.625,57.775 54.125,58.775 55.255,59.275 0.624,59.55 53.625,59.775 54.625,59.775 54.125,60.775 55.255,61.25 0.624,61.525 53.625,61.775 54.625,61.775 4.025,62.325 54.125,62.775 55.255,63.225 0.624,63.5 53.625,63.775 54.625,63.775 54.125,64.775 55.255,65.2 0.624,65.475 53.625,65.775 54.625,65.775 53.125,66.775 54.125,66.775 55.255,67.175 0.624,67.45 53.625,67.775 54.625,67.775 4.125,68.6 53.125,68.775 54.125,68.775 55.255,69.15 0.624,69.425 52.625,69.775 53.625,69.775 54.625,69.775 52.125,70.775 53.125,70.775 54.125,70.775 55.255,71.125 0.624,71.4 52.625,71.775 53.625,71.775 54.625,71.775 4,72.275 53.125,72.775 54.125,72.775 55.255,73.1 0.624,73.375 52.625,73.775 53.625,73.775 54.625,73.775 40.125,74.775 52.125,74.775 53.125,74.775 54.125,74.775 55.255,75.075 4.075,75.325 0.625,75.35 52.625,75.775 53.625,75.775 54.625,75.775 52.125,76.775 53.125,76.775 54.125,76.775 55.255,77.05 0.625,77.325 39.625,77.775 52.625,77.775 53.625,77.775 54.625,77.775 52.125,78.775 53.125,78.775 54.125,78.775 4.05,78.975 55.256,79.025 0.625,79.3 52.625,79.775 53.625,79.775 54.625,79.775 52.125,80.775 53.125,80.775 54.125,80.775 55.256,81 0.625,81.275 16.625,81.775 52.625,81.775 53.625,81.775 54.625,81.775 4,82.325 53.125,82.775 54.125,82.775 55.256,82.975 25.775,83.15 0.625,83.25 52.625,83.775 53.625,83.775 54.625,83.775 47.975,84.25 53.125,84.775 54.125,84.775 33.45,84.9 55.256,84.95 39.725,85.15 0.625,85.225 25.4,85.525 35.25,85.725 52.625,85.775 53.625,85.775 54.625,85.775 3.975,85.975 53.125,86.775 54.125,86.775 55.256,86.925 26.575,87.05 0.625,87.2 52.625,87.775 53.625,87.775 54.625,87.775 37.6,87.825 53.125,88.775 54.125,88.775 55.256,88.9 0.625,89.175 24.625,89.35 20.45,89.45 52.625,89.775 53.625,89.775 54.625,89.775 4,90.225 53.125,90.775 54.125,90.775 55.256,90.875 37.85,91.075 0.625,91.15 17.85,91.225 23.15,91.325 26.575,91.325 41.875,91.65 45.675,91.675 52.625,91.775 53.625,91.775 54.625,91.775 52.125,92.775 53.125,92.775 54.125,92.775 55.256,92.85 0.625,93.125 42.625,93.2 34.425,93.75 52.625,93.775 53.625,93.775 54.625,93.775 3.65,94.625 52.125,94.775 53.125,94.775 54.125,94.775 55.256,94.825 0.625,95.1 52.625,95.775 53.625,95.775 54.625,95.775 17.464,96.104 20.614,96.104 52.125,96.775 53.125,96.775 54.125,96.775 55.256,96.8 16.15,96.975 0.625,97.075 24.85,97.4 17.45,97.425 20.625,97.575 52.625,97.775 53.625,97.775 54.625,97.775 3.65,97.975 17.839,98.054 20.264,98.129 16.175,98.375 20.425,98.675 25.125,98.775 26.125,98.775 53.125,98.775 54.125,98.775 55.256,98.775 17.214,98.829 0.625,99.05 52.625,99.775 53.625,99.775 54.625,99.775 41.3,100.35 42.45,100.35 55.256,100.75 10.625,100.875 0.625,101.025 22.15,101.1 24.125,101.2 26.5,101.675 17.625,101.775 18.625,101.775 52.275,102.05 41.3,102.275 42.45,102.275 55.256,102.725 28.2,102.75 0.625,103 26.5,103 55.256,104.7 17.9,104.725 22.75,104.725 24.175,104.725 0.625,104.975 53.525,106.45 55.256,106.675 0.625,106.95 39.575,107.175 29.275,107.25 24.25,108.35 26.45,108.425 55.256,108.65 0.625,108.925 55.256,110.625 0.625,110.9 3.725,110.95 4.525,110.95 2.9,110.975 31.275,111.075 53.575,111.35 24.25,111.65 26.425,111.675 1.625,111.775 2.625,111.775 12.525,111.925 19.45,112.375 55.256,112.6 2.125,112.775 3.125,112.775 0.625,112.875 12.825,113.1 25.45,113.625 55.256,114.575 26.125,114.775 27.125,114.775 34.125,114.775 0.625,114.85 16.725,115.125 21.95,115.125 18.375,115.175 13.45,115.4 32,115.525 26.625,115.775 25.4,116.2 55.256,116.55 0.625,116.825 44.05,117.3 47.85,117.425 26.5,117.45 10.725,117.975 12.325,117.975 13.675,117.975 28.875,118.35 10.7,118.425 55.256,118.525 0.625,118.8 48.175,119.475 35.5,119.525 55.256,120.5 0.625,120.775 38.625,121.175 27.6,121.55 41.8,122.45 55.256,122.475 28.825,122.6 10.875,122.675 11.475,122.675 12.1,122.675 12.675,122.675 13.225,122.675 13.85,122.675 0.625,122.75 10.875,123.275 11.475,123.275 12.1,123.275 12.675,123.275 13.2,123.275 13.825,123.275 10.875,123.825 11.455,123.819 12.1,123.825 12.675,123.825 13.2,123.825 13.675,123.825 40.175,124.375 55.256,124.45 47.5,124.65 0.625,124.725 22.5,126.4 40.875,126.41 55.256,126.425 0.625,126.7 18.55,127.25 46.6,127.325 55.256,128.4 23.475,128.425 0.625,128.675 44.4,128.95 55.256,130.375 16.775,130.55 0.625,130.65 41.4,130.875 25.525,131.65 55.256,132.35 0.625,132.625 19.125,132.775 25.85,133.425 42.7,133.925 55.256,134.325 0.625,134.6 21.8,135.875 19.05,136.025 55.256,136.3 9.325,136.35 0.625,136.575 2.125,136.775 3.125,136.775 5.125,136.775 10.125,136.775 21.875,137.2 14.725,137.725 1.625,137.775 2.625,137.775 3.625,137.775 4.625,137.775 9.625,137.775 10.625,137.775 55.256,138.275 0.625,138.55 2.125,138.775 3.125,138.775 4.125,138.775 5.125,138.775 6.125,138.775 7.125,138.775 8.125,138.775 9.125,138.775 10.125,138.775 22.6,139.175 24.4,139.2 48.45,139.35 25.75,140.2 55.256,140.25 0.625,140.525 46,140.55 1.125,140.775 10.125,140.775 23.725,141.225 10.15,141.625 55.256,142.225 0.625,142.5 1.125,142.775 2.63,142.769 4.125,142.775 5.125,142.775 6.125,142.775 7.125,142.775 8.125,142.775 9.125,142.775 10.125,142.775 20.125,142.775 1.625,143.775 3.625,143.775 5.625,143.775 6.625,143.775 7.625,143.775 9.625,143.775 10.625,143.775 19.625,143.775 20.625,143.775 4.775,144.025 8.75,144.025 55.256,144.2 46.35,144.3 0.625,144.475 1.125,144.775 2.125,144.775 3.125,144.775 4.125,144.775 5.125,144.775 7.125,144.775 8.125,144.775 9.125,144.775 21.125,144.775 45.85,145.55 1.625,145.775 3.625,145.775 4.625,145.775 9.625,145.775 20.625,145.775 21.625,145.775 22.625,145.775 23.5,145.825 2.975,145.925 9.075,146.05 55.256,146.175 0.625,146.45 33.675,146.675 1.125,146.775 2.125,146.775 3.125,146.775 4.125,146.775 5.125,146.775 8.125,146.775 9.125,146.775 22.125,146.775 23.125,146.775 40.125,146.775 20.875,146.85 25.7,147.65 1.625,147.775 2.625,147.775 3.625,147.775 4.625,147.775 8.625,147.775 21.625,147.775 22.625,147.775 23.35,147.9 36.825,148.075 32.95,148.15 55.256,148.15 0.625,148.425 1.125,148.775 2.125,148.775 3.125,148.775 4.125,148.775 8.125,148.775 22.125,148.775 23.125,148.775 29.1,148.8 8.9,149 40.375,149.425 39.225,149.475 3.625,149.775 4.625,149.775 8.625,149.775 22.625,149.775 35.925,149.95 22,150.075 55.256,150.125 3.125,150.775 4.125,150.775 5.125,150.775 6.125,150.775 7.125,150.775 8.125,150.775 23.125,150.775 2.275,151.775 4.25,151.775 6.225,151.775 24.4,151.775 26.375,151.775 28.35,151.775 30.325,151.775 32.3,151.775 34.275,151.775 36.25,151.775 47.955,151.775 49.93,151.775 51.905,151.775
  other v2: 12.4,119.45 13.5,119.45 11.3,120.55 13.5,120.55 12.4,121.65 13.5,121.65
GNDDet: SW1.11 U9.K13 | length 28.9
  Top Layer w0.15: U9.K13@37.98,141.725 38.31,142.055 38.31,143.355 v1(38.605,143.65)
  Top Layer w0.3: v1(26.325,136.58) SW1.11@27.86,136.58 SW1.11@27.92,136.58 ; v1(28.955,147.27) 38.435,147.27 v1(38.605,147.1)
  Bottom Layer w0.3: v1(26.325,136.58) 27.925,138.18 27.925,139.945 28.955,140.975 v1(28.955,147.27) ; v1(38.605,143.65) 38.605,144.275 38.455,144.425 38.455,145.975 38.605,146.125 v1(38.605,147.1)
GNDDetect: CN1.11 R106.2 SW1.3 | length 43.1
  Top Layer w0.3: SW1.3@20.105,136.58 SW1.3@20.24,136.58 22.335,136.58 v1(22.34,136.575) ; v1(28.675,112.575) 28.675,111.925 28.675,111.812 29.459,111.028 30.266,111.028 30.837,111.6 33.425,111.6 34.05,112.225 35.98,112.225 v1(36.005,112.25) ; v1(36,114.557) R106.2@36,115.285 36.175,115.46 CN1.11@36.175,117.493
  Bottom Layer w0.3: v1(22.34,136.575) 22.34,130.44 26.105,126.675 26.105,118.775 28.675,116.205 v1(28.675,112.575) ; v1@35.975,114.582 v1(36,114.557) 36,112.245 v1(36.005,112.25)
GREEN_LED_K: LD1.3 SB9.2 | length 33.4
  Top Layer w0.5: v1(30.75,64.3) v1@30.75,64.325 ; SB9.2@40.35,64.325 SB9.2@40.225,64.325 ; v1@30.75,64.325 29.925,64.325 29.7,64.55 LD1.3@29.7,64.75 v1(30.75,64.75) v1@30.75,64.325 ; SB9.2@40.225,64.325 v1(39.375,64.325) 39.35,64.35 v1(39.35,65) 39.55,65 SB9.2@40.225,64.325
  Signal Layer 2 w0.5: v1@39.375,64.3 v1(30.75,64.3) v1(30.75,64.75) ; v1(39.375,64.325) v1@39.375,64.375 ; v1@39.425,64.325 v1@39.375,64.375 ; v1(30.75,64.75) 39,64.75 v1@39.375,64.375 ; v1(30.75,64.75) 31,65 v1(39.35,65) 39.375,64.975 v1@39.375,64.375
  Bottom Layer w0.5: v1(30.75,64.3) v1(30.75,64.75)
JOYSTICK_DOWN: B2.3 C15.2 SB6.2 U1.4 | length 8.2
  Top Layer w0.12: SB6.2@13.55,48.475 C15.2@13.55,47.3 v1(14.2,47.3) ; U1.4@15.775,44.6 15.775,45.375 15.275,45.875 v1(15.275,47.3) 16.43,47.3 B2.3@17.298,48.168
  Bottom Layer w0.12: v1(14.2,47.3) v1(15.275,47.3)
JOYSTICK_LEFT: B2.1 C10.2 SB2.1 U1.6 | length 11.5
  Top Layer w0.12: SB2.1@13.45,43.875 C10.2@13.45,42.7 14.35,42.7 14.625,42.975 ; B2.1@15.318,50.148 14.625,49.455 14.625,42.975 ; U1.6@15.45,42.7 U1.6@15.775,42.7 14.9,42.7 14.625,42.975
JOYSTICK_RIGHT: B2.6 C11.2 SB3.1 U1.1 | length 17.4
  Top Layer w0.12: U1.1@18.075,42.7 19.45,42.7 19.625,42.875 ; SB3.1@21.45,43.85 C11.2@21.45,42.7 19.8,42.7 19.625,42.875 ; B2.6@21.682,52.552 20.93,51.8 18.825,51.8 18.425,51.4 18.425,49.589 19.15,48.864 19.15,45.4 19.625,44.925 19.625,42.875
JOYSTICK_SELECT: B2.2 C12.2 SB5.2 U1.5 | length 10.1
  Top Layer w0.12: SB5.2@13.55,46.175 C12.2@13.55,45 v1(14.2,45) ; U1.5@15.775,43.65 15.065,43.65 14.865,43.85 14.865,45.065 v1(15.15,45.35) 14.865,45.635 14.865,47.715 B2.2@16.308,49.158
  Bottom Layer w0.12: v1(14.2,45) 14.55,45.35 v1(15.15,45.35)
JOYSTICK_UP: B2.4 C13.2 SB4.1 U1.3 | length 15.7
  Top Layer w0.12: U1.3@18.075,44.6 v1(19.15,44.6) 19.15,45.061 18.91,45.301 18.91,48.765 18.175,49.5 18.175,51.489 18.675,51.989 18.675,53.505 B2.4@19.702,54.532 ; v1(20.8,45) C13.2@21.45,45 SB4.1@21.45,46.15
  Bottom Layer w0.12: v1(19.15,44.6) 19.55,45 v1(20.8,45)
LED_DOWN_BLUE: LD2.1 R89.2 | length 59.1
  Top Layer w0.12: v1(5.153,73.65) 5.153,88.701 v1(5.425,88.973) ; v1(10.175,94.35) 10.23,94.35 10.375,94.205 10.375,94.125 R89.2@11.225,94.125 ; v1(15.325,72.425) 15.473,72.573 19.879,72.573 20.868,73.562 37.188,73.562 37.55,73.2 LD2.1@37.775,73.2
  Bottom Layer w0.12: v1(5.153,73.65) 7.525,73.65 8.75,72.425 v1(15.325,72.425) ; v1(5.425,88.973) 7.798,88.973 9.425,90.6 9.425,93.6 v1(10.175,94.35)
LED_LEFT_ORANGE: LD3.1 R80.1 | length 1.3
  Top Layer w0.45: R80.1@34.725,74.35 LD3.1@34.725,75.65
LED_RIGHT_GREEN: LD4.1 R81.1 | length 1.3
  Top Layer w0.45: LD4.1@40.2,75.65 R81.1@40.2,76.95
LED_STLK: R128.2 R129.2 U9.D15 | length 27.5
  Top Layer w0.12: v1@33.05,143.895 33.68,143.895 34.085,143.49 34.085,143.03 U9.D15@34.08,143.025 U9.D15@34.075,143.02 ; v1(54.4,141) R128.2@54.4,141.925 R129.2@54.4,143.425
  Bottom Layer w0.2: v1(33.05,143.92) 34.795,142.175 40.825,142.175 41.8,143.15 52.25,143.15 v1(54.4,141)
LED_UP_RED: LD5.1 R82.1 | length 1.1
  Top Layer w0.45: R82.1@36.375,78.375 LD5.1@37.45,78.375
MCO: C84.2 R130.2 SB36.1 | length 83.5
  Top Layer w0.12: v1(29.68,146.675) 31.13,146.675 31.48,146.325 ; C84.2@31.48,145.4 31.48,146.325 ; R130.2@33.305,145.45 33.305,146.3 32.905,146.7 31.855,146.7 31.48,146.325
  Bottom Layer w0.12: SB36.1@18.814,84.354 18.464,84.704 18.464,88.089 19.075,88.7 22.275,88.7 24.375,90.8 24.375,95.275 26.725,97.625 32.18,97.625 34.85,100.295 34.85,106.62 36.225,107.995 36.225,111.375 35.425,112.175 35.425,116.2 34.85,116.775 34.85,125.18 29.68,130.35 v1(29.68,146.675)
NetB1_1: B1.1 B1.2 R67.2 | length 11.3
  Top Layer w0.3: R67.2@35.575,45.775 B1.1@37.375,45.775 B1.2@37.375,55.275
NetB2_5: B2.5 R70.2 | length 2.1
  Top Layer w0.3: B2.5@20.692,53.542 22.175,55.025 R70.2@22.2,55.025
NetC17_1: C17.1 L2.2 SB7.1 | length 6.5
  Top Layer w0.7: L2.2@29.325,52.65 29.6,52.375 31.15,52.375 SB7.1@31.45,52.075 31.45,53.375 C17.1@31.25,53.575 29.85,53.575 29.325,53.05 L2.2@29.325,52.65
NetC20_1: C20.1 L3.2 SB9.1 | length 6.4
  Top Layer w0.5: L3.2@38.145,66.425 38.845,65.725 40.05,65.725 SB9.1@40.35,65.425 40.35,66.72 C20.1@40.145,66.925 38.645,66.925 L3.2@38.145,66.425
NetC21_1: C21.1 L4.2 SB8.1 | length 5.9
  Top Layer w0.65: L4.2@19.85,66.425 20.475,65.8 21.275,65.8 21.65,65.425 SB8.1@21.75,65.425 C21.1@21.75,66.925 20.35,66.925 L4.2@19.85,66.425
NetC26_2: C26.2 L5.1 SB17.2 SB18.2 | length 4.5
  Top Layer w0.45: L5.1@32.989,86.529 C26.2@34.414,86.529 35.314,86.529 SB17.2@35.564,86.779 37.346,86.779 SB18.2@37.35,86.775
NetC41_2: C41.2 R97.2 TP4.1 | length 4.4
  Top Layer w0.5: C41.2@29.75,104.2 R97.2@29.75,103.05 30.5,103.05 TP4.1@32.3,101.25
NetC42_2: C42.2 C43.2 D9.2 D10.2 D11.2 U5.1 U5.3 | length 12.4
  Top Layer w0.3: 39.025,109.525 39.13,109.63 ; D9.2@39.13,106.205 39.13,106.845
  Top Layer w0.5: U5.1@31.975,106.125 31.975,106.7 32.5,107.225 33.459,107.225 33.875,106.809 U5.3@33.875,106.125 34.325,106.575 C43.2@35.15,106.575 C42.2@36.275,106.575 ; 36.35,109.05 36.335,109.035 D10.2@36.335,108.205 36.335,106.635 C42.2@36.275,106.575 ; D9.2@39.13,106.205 37.57,106.205 37.2,106.575 C42.2@36.275,106.575
NetC44_2: C44.2 U5.4 | length 1.5
  Top Layer w0.5: U5.4@33.875,108.325 34.35,107.85 C44.2@35.175,107.85
NetC46_2: C46.2 R100.1 | length 1.4
  Top Layer w0.65: R100.1@8.25,111.125 9.375,111.125 C46.2@9.55,110.95
NetC57_1: C57.1 U6.12 | length 15.5
  Top Layer w0.3: U6.12@15.175,120.225 16.2,120.225 v1(16.225,120.2)
  Top Layer w0.65: v1(6.025,124.075) C57.1@6.875,124.075
  Bottom Layer w0.3: v1(6.025,124.075) 6.4,124.45 14.55,124.45 16.225,122.775 v1(16.225,120.2)
NetC58_1: C58.1 U6.13 | length 8.1
  Top Layer w0.4: U6.13@15.175,120.875 17.65,120.875 v1(17.925,120.6) ; C58.1@17.9,124.1 C58.1@17.925,124.075
  Top Layer w0.65: C58.1@17.9,124.1 v1(17.9,124.925)
  Bottom Layer w0.4: v1(17.9,124.925) 17.9,120.625 v1(17.925,120.6)
NetC74_2: C74.2 U9.M10 | length 9.5
  Top Layer w0.25: 38.91,139.775 U9.M10@39.28,139.775
  Top Layer w0.3: v1(38.685,140) 38.91,139.775 ; v1(41.86,140.1) 45.105,140.1 45.88,139.325 C74.2@47.105,139.325
  Bottom Layer w0.3: v1(38.685,140) 38.785,140.1 v1(41.86,140.1)
NetC78_2: C78.2 U9.F13 | length 6.2
  Top Layer w0.12: 31.605,142.35 31.905,142.05 35.055,142.05 U9.F13@35.38,141.725
  Top Layer w0.3: C78.2@29.83,143.3 30.655,143.3 31.605,142.35
NetC82_2: C82.2 U9.J14 | length 2.6
  Top Layer w0.15: U9.J14@37.33,142.375 37.66,142.705 37.66,143.305 37.78,143.425
  Top Layer w0.3: 37.78,143.425 38.055,143.7 C82.2@38.055,144.625
NetC89_2: C89.2 R135.2 R136.1 U16.3 | length 5.1
  Bottom Layer w0.4: C89.2@9.975,80.975 10.8,80.15 R136.1@10.8,79.175 R135.2@11.75,79.175 11.65,79.075 U16.3@11.65,77.2
NetC94_1: C94.1 Q11.1 R137.1 U17.3 | length 9.7
  Bottom Layer w0.45: Q11.1@41.925,82.55 43.025,83.65 43.025,84.6 43.325,84.9 R137.1@46.525,84.9 C94.1@46.525,86.775 46.525,87.875 U17.3@46.925,88.275
NetC94_2: C94.2 R138.1 R139.2 SB37.1 U17.4 | length 6.2
  Bottom Layer w0.45: SB37.1@42.975,85.95 43.4,86.375 R138.1@43.4,87.35 43.4,88.3 R139.2@43.175,88.525 44.475,88.525 U17.4@44.725,88.275 44.725,87.175 C94.2@45.125,86.775
NetC102_1: C102.1 Q12.4 Q13.4 R140.2 R142.2 | length 14.5
  Top Layer w0.4: v1(5.075,105) 7.075,105 ; v1(5.075,108.75) 6.35,108.75 7.075,108.025 7.075,105 ; v1(9.175,105) 7.075,105
  Bottom Layer w0.4: Q13.4@4.5,105 v1(5.075,105) ; Q12.4@8.6,105 v1(9.175,105)
  Bottom Layer w0.5: C102.1@2.55,109.175 2.975,108.75 R140.2@4.15,108.75 ; R142.2@4.15,109.925 R140.2@4.15,108.75 ; v1(5.075,108.75) R140.2@4.15,108.75
NetC102_2: C102.2 Q12.1 Q12.2 Q12.3 Q13.1 Q13.2 Q13.3 R140.1 | length 5.5
  Bottom Layer w0.3: Q13.1@2.55,105 Q13.2@3.2,105 Q13.3@3.85,105 ; Q12.1@6.65,105 Q12.2@7.3,105 Q12.3@7.95,105 7.95,104.425 7.85,104.325 7.65,104.325
  Bottom Layer w0.5: 2.55,106.4 C102.2@2.55,107.475 ; 4.15,106.45 R140.1@4.15,107.35
NetD1_1: D1.1 R10.2 R16.1 | length 4.3
  Top Layer w0.5: R10.2@10.075,4.4 R16.1@10.075,6.025 10.075,8.195 D1.1@10.405,8.525
NetD2_1: D2.1 R15.1 | length 1.9
  Top Layer w0.5: R15.1@40.525,6.95 41.4,7.825 D2.1@41.4,8.525
NetD2_3: D2.3 D3.1 R14.1 T6.3 | length 9.3
  Top Layer w0.5: T6.3@38.15,13.85 39.11,13.85 D3.1@40.675,12.285 40.675,12.225 39.2,10.75 D2.3@39.2,9.475 39.2,7.475 R14.1@38.675,6.95
NetD4_1: D4.1 R28.2 | length 1.9
  Top Layer w0.5: D4.1@23.15,21.925 24.65,21.925 R28.2@24.925,22.2
NetD4_3: D4.3 D5.1 R27.2 T5.3 | length 9
  Top Layer w0.5: D5.1@19.49,21.125 19.49,20.885 20.65,19.725 D4.3@22.2,19.725 23.05,19.725 23.525,19.25 R27.2@23.525,18.775 23.525,16.625 24,16.15 T5.3@24.775,16.15
NetD6_1: D6.1 L2.1 T9.1 T9.2 T9.5 T9.6 T9.8 | length 20
  Top Layer w0.3: L2.1@25.725,53.05 L2.1@25.725,51.65 ; 27.025,51.15 26.925,51.25 ; L2.1@25.725,51.65 25.725,51.25 26.925,51.25 ; L2.1@25.725,51.65 25.325,51.25 24.4,51.25 24.225,51.425 24.225,54.525 24.55,54.85 27.025,54.85 27.175,54.7 27.175,51.6 26.925,51.35 26.925,51.25 ; T9.8@26.088,49.025 26.438,49.375 T9.6@26.975,49.375 T9.5@26.975,48.725 26.388,48.725 T9.8@26.088,49.025 ; T9.8@26.088,49.025 25.788,48.725 25.225,48.725 25.225,49.375 25.738,49.375 T9.8@26.088,49.025
NetD7_1: D7.1 L4.1 T11.1 T11.2 T11.5 T11.6 T11.8
NetD8_1: D8.1 L3.1 T10.1 T10.2 T10.5 T10.6 T10.8
NetD10_1: D10.1 SB31.2
NetF1_1: F1.1 R40.2 R48.2 R56.2 R64.2
NetF2_1: F2.1 R32.2 R36.2 R44.2 R52.2
NetJP2_1: JP2.1 R24.1 T1.1 T1.2 T1.5 T1.6 T1.8 T5.1 T5.2 T5.5 T5.6
NetJP2_2: JP2.2 L1.2 R24.2 | length 6.4
  Top Layer w0.4: R24.2@28.1,11.375 R24.2@28.2,11.375 28.525,11.375
  Top Layer w1: 28.525,11.375 29.9,11.375 JP2.2@29.9,15.955
NetJP3_1: JP3.1 L1.1 R25.1 | length 5.8
  Top Layer w1: JP3.1@33.5,15.955 33.5,11.375 34.7,11.375
NetJP3_2: JP3.2 R25.2 T2.1 T2.2 T2.5 T2.6 T2.8 T6.1 T6.2 T6.5 T6.6
NetJP7_2: JP7.2 R115.1 | length 15.8
  Top Layer w0.12: R115.1@37.075,124.632 37.628,125.185 49.465,125.185 49.48,125.2 49.505,125.175 v1(49.53,125.175)
  Bottom Layer w0.12: JP7.2@49.525,128.27 49.53,128.265 v1(49.53,125.175)
NetL6_1: L6.1 SB17.1 SB21.2 SB22.2 | length 6.4
  Top Layer w0.3: L6.1@32.714,91.854 33.325,91.243 33.325,89.75 33.496,89.579 SB21.2@34.164,89.579
  Top Layer w0.45: SB21.2@34.114,89.529 SB21.2@34.164,89.579 SB22.2@35.564,89.579 SB17.1@35.564,87.879
NetLD6_1: LD6.1 R92.1 | length 1.4
  Top Layer w0.6: LD6.1@40.2,96.225 40.325,96.1 R92.1@41.5,96.1
NetLD7_1: LD7.1 R104.1 | length 1.8
  Top Layer w0.65: LD7.1@43.825,115.275 R104.1@45.6,115.275
NetLD8_1: LD8.1 R121.1 | length 1.3
  Top Layer w0.3: R121.1@54.23,135.625 LD8.1@54.23,136.925
NetLD8_2: LD8.2 R119.1 U10.3 | length 7.7
  Top Layer w0.3: R119.1@48.73,133.5 48.73,136.55 49.105,136.925 U10.3@49.905,136.925 50.105,136.925 50.655,137.475 52.18,137.475 LD8.2@52.73,136.925
NetLD9_2: LD9.2 R129.1 | length 1.4
  Top Layer w0.3: LD9.2@51.575,143.425 R129.1@53,143.425
NetLD9_3: LD9.3 R128.1 | length 1.4
  Top Layer w0.3: LD9.3@51.575,141.925 R128.1@53,141.925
